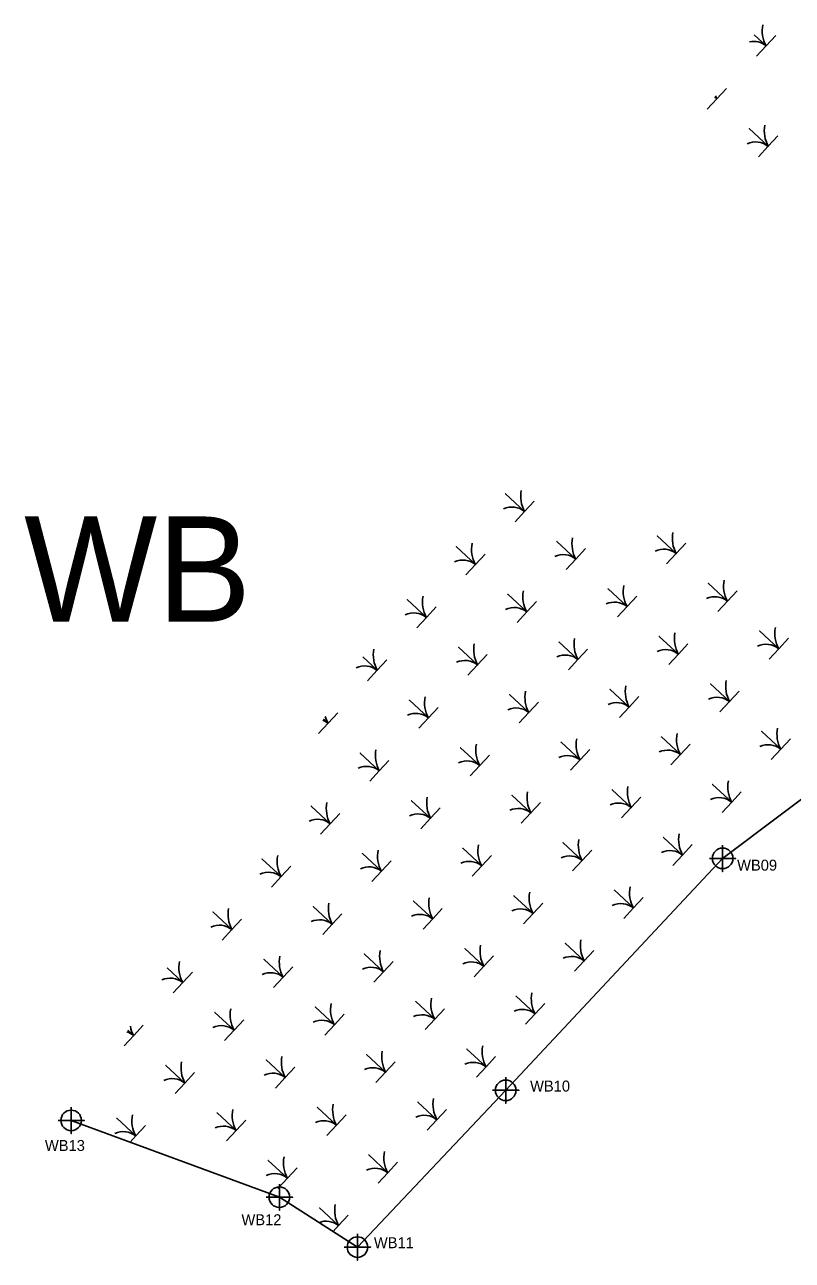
# Model space of a CAD drawing. Extents: x 2130226 to 2130625, y 149525 to 150037.
# Drawn here: x 2130226.4 to 2130401.2, y 149726.8 to 150008.2 of the extents above; entities that cross this region are included whole.
import ezdxf

# ---------------------------------------------------------------- set-up
doc = ezdxf.new("R2010")
doc.units = 0
for name, color, linetype in [('Default', 7, 'Continuous'), ('Exist Environmental Wetland Boundary', 7, 'Continuous'), ('Exist Environmental Wetland Boundary Cogo Number', 7, 'Continuous'), ('Exist Environmental Wetland Boundary Cogo Point CELL', 7, 'Continuous')]:
    doc.layers.add(name, color=color, linetype=linetype)

msp = doc.modelspace()

# ---------------------------------------------------------------- linework, layer by layer
at = {"layer": 'Exist Environmental Wetland Boundary'}
msp.add_lwpolyline([(2130236.94, 149758.63), (2130284.36, 149741.14), (2130302.13, 149729.77), (2130335.9, 149765.49), (2130385.31, 149818.32), (2130425.92, 149848.84), (2130446.29, 149863.99), (2130449.73, 149867.45)], dxfattribs=at)
at = {"layer": 'Exist Environmental Wetland Boundary Cogo Point CELL'}
for points in [[(2130393.01, 150001.04), (2130395.21, 150003.4), (2130392.47, 150005.94)], [(2130392.47, 150005.94), (2130395.21, 150003.4), (2130397.4, 150005.76)], [(2130383.56, 149991.77), (2130384.02, 149991.34), (2130386.21, 149993.7)], [(2130381.82, 149988.98), (2130384.02, 149991.34), (2130383.56, 149991.77)], [(2130393.49, 149978.15), (2130395.69, 149980.51), (2130391.35, 149984.54), (2130395.69, 149980.51), (2130397.88, 149982.88)], [(2130338.02, 149894.97), (2130340.21, 149897.33), (2130335.88, 149901.36), (2130340.21, 149897.33), (2130342.41, 149899.69)], [(2130326.83, 149882.91), (2130329.02, 149885.27), (2130324.69, 149889.3), (2130329.02, 149885.27), (2130331.22, 149887.64)], [(2130349.69, 149884.14), (2130351.88, 149886.5), (2130347.55, 149890.53), (2130351.88, 149886.5), (2130354.08, 149888.87)], [(2130372.55, 149885.37), (2130374.74, 149887.74), (2130370.4, 149891.76), (2130374.74, 149887.74), (2130376.94, 149890.1)], [(2130384.22, 149874.54), (2130386.41, 149876.91), (2130382.07, 149880.93), (2130386.41, 149876.91), (2130388.6, 149879.27)], [(2130338.5, 149872.08), (2130340.69, 149874.44), (2130336.36, 149878.47), (2130340.69, 149874.44), (2130342.89, 149876.81)], [(2130361.36, 149873.31), (2130363.55, 149875.68), (2130359.21, 149879.7), (2130363.55, 149875.68), (2130365.75, 149878.04)], [(2130315.64, 149870.85), (2130317.83, 149873.21), (2130313.5, 149877.24), (2130317.83, 149873.21), (2130320.03, 149875.58)], [(2130395.88, 149863.72), (2130398.08, 149866.08), (2130393.74, 149870.11), (2130398.08, 149866.08), (2130400.27, 149868.45)], [(2130350.17, 149861.25), (2130352.36, 149863.62), (2130348.02, 149867.64), (2130352.36, 149863.62), (2130354.56, 149865.98)], [(2130373.03, 149862.48), (2130375.22, 149864.85), (2130370.88, 149868.87), (2130375.22, 149864.85), (2130377.41, 149867.21)], [(2130304.45, 149858.79), (2130306.64, 149861.15), (2130303.34, 149864.22)], [(2130303.34, 149864.22), (2130306.64, 149861.15), (2130308.84, 149863.52)], [(2130327.31, 149860.02), (2130329.5, 149862.38), (2130325.17, 149866.41), (2130329.5, 149862.38), (2130331.7, 149864.75)], [(2130384.69, 149851.66), (2130386.89, 149854.02), (2130382.55, 149858.05), (2130386.89, 149854.02), (2130389.08, 149856.39)], [(2130338.98, 149849.19), (2130341.17, 149851.56), (2130336.83, 149855.58), (2130341.17, 149851.56), (2130343.37, 149853.92)], [(2130361.84, 149850.43), (2130364.03, 149852.79), (2130359.69, 149856.81), (2130364.03, 149852.79), (2130366.22, 149855.15)], [(2130316.12, 149847.96), (2130318.31, 149850.33), (2130313.98, 149854.35), (2130318.31, 149850.33), (2130320.51, 149852.69)], [(2130293.26, 149846.73), (2130295.45, 149849.09), (2130294.43, 149850.05)], [(2130294.43, 149850.05), (2130295.45, 149849.09), (2130297.65, 149851.46)], [(2130396.36, 149840.83), (2130398.56, 149843.19), (2130394.22, 149847.22), (2130398.56, 149843.19), (2130400.75, 149845.56)], [(2130350.65, 149838.37), (2130352.84, 149840.73), (2130348.5, 149844.76), (2130352.84, 149840.73), (2130355.03, 149843.09)], [(2130373.5, 149839.6), (2130375.7, 149841.96), (2130371.36, 149845.99), (2130375.7, 149841.96), (2130377.89, 149844.33)], [(2130304.93, 149835.9), (2130307.12, 149838.27), (2130302.79, 149842.29), (2130307.12, 149838.27), (2130309.32, 149840.63)], [(2130327.79, 149837.13), (2130329.98, 149839.5), (2130325.64, 149843.52), (2130329.98, 149839.5), (2130332.18, 149841.86)], [(2130362.31, 149827.54), (2130364.51, 149829.9), (2130360.17, 149833.93), (2130364.51, 149829.9), (2130366.7, 149832.27)], [(2130385.17, 149828.77), (2130387.37, 149831.14), (2130383.03, 149835.16), (2130387.37, 149831.14), (2130389.56, 149833.5)], [(2130293.74, 149823.84), (2130295.93, 149826.21), (2130291.6, 149830.23), (2130295.93, 149826.21), (2130298.13, 149828.57)], [(2130316.6, 149825.07), (2130318.79, 149827.44), (2130314.45, 149831.46), (2130318.79, 149827.44), (2130320.99, 149829.8)], [(2130339.46, 149826.31), (2130341.65, 149828.67), (2130337.31, 149832.7), (2130341.65, 149828.67), (2130343.84, 149831.04)], [(2130351.12, 149815.48), (2130353.32, 149817.84), (2130348.98, 149821.87), (2130353.32, 149817.84), (2130355.51, 149820.21)], [(2130373.98, 149816.71), (2130376.18, 149819.08), (2130371.84, 149823.1), (2130376.18, 149819.08), (2130378.37, 149821.44)], [(2130305.41, 149813.02), (2130307.6, 149815.38), (2130303.26, 149819.4), (2130307.6, 149815.38), (2130309.8, 149817.74)], [(2130328.27, 149814.25), (2130330.46, 149816.61), (2130326.12, 149820.64), (2130330.46, 149816.61), (2130332.65, 149818.98)], [(2130385.31, 149821.32), (2130385.31, 149815.32), (2130385.31, 149818.32), (2130388.31, 149818.32), (2130382.31, 149818.32)], [(2130282.55, 149811.78), (2130284.74, 149814.15), (2130280.41, 149818.17), (2130284.74, 149814.15), (2130286.94, 149816.51)], [(2130362.79, 149804.65), (2130364.99, 149807.02), (2130360.65, 149811.04), (2130364.99, 149807.02), (2130367.18, 149809.38)], [(2130317.08, 149802.19), (2130319.27, 149804.55), (2130314.93, 149808.58), (2130319.27, 149804.55), (2130321.46, 149806.92)], [(2130339.93, 149803.42), (2130342.13, 149805.78), (2130337.79, 149809.81), (2130342.13, 149805.78), (2130344.32, 149808.15)], [(2130271.36, 149799.72), (2130273.55, 149802.09), (2130269.22, 149806.11), (2130273.55, 149802.09), (2130275.75, 149804.45)], [(2130294.22, 149800.96), (2130296.41, 149803.32), (2130292.07, 149807.35), (2130296.41, 149803.32), (2130298.61, 149805.68)], [(2130351.6, 149792.59), (2130353.8, 149794.96), (2130349.46, 149798.98), (2130353.8, 149794.96), (2130355.99, 149797.32)], [(2130305.89, 149790.13), (2130308.08, 149792.49), (2130303.74, 149796.52), (2130308.08, 149792.49), (2130310.27, 149794.86)], [(2130328.74, 149791.36), (2130330.94, 149793.73), (2130326.6, 149797.75), (2130330.94, 149793.73), (2130333.13, 149796.09)], [(2130260.17, 149787.66), (2130262.36, 149790.03), (2130258.78, 149793.36)], [(2130258.78, 149793.36), (2130262.36, 149790.03), (2130264.56, 149792.39)], [(2130283.03, 149788.9), (2130285.22, 149791.26), (2130280.88, 149795.29), (2130285.22, 149791.26), (2130287.42, 149793.63)], [(2130317.55, 149779.3), (2130319.75, 149781.67), (2130315.41, 149785.69), (2130319.75, 149781.67), (2130321.94, 149784.03)], [(2130340.41, 149780.53), (2130342.61, 149782.9), (2130338.27, 149786.92), (2130342.61, 149782.9), (2130344.8, 149785.26)], [(2130271.84, 149776.84), (2130274.03, 149779.2), (2130269.69, 149783.23), (2130274.03, 149779.2), (2130276.23, 149781.57)], [(2130294.7, 149778.07), (2130296.89, 149780.43), (2130292.55, 149784.46), (2130296.89, 149780.43), (2130299.08, 149782.8)], [(2130249.86, 149779.18), (2130251.17, 149777.97), (2130253.37, 149780.33)], [(2130248.98, 149775.61), (2130251.17, 149777.97), (2130249.86, 149779.18)], [(2130306.36, 149767.24), (2130308.56, 149769.61), (2130304.22, 149773.63), (2130308.56, 149769.61), (2130310.75, 149771.97)], [(2130329.22, 149768.47), (2130331.42, 149770.84), (2130327.08, 149774.86), (2130331.42, 149770.84), (2130333.61, 149773.2)], [(2130260.65, 149764.78), (2130262.84, 149767.14), (2130258.5, 149771.17), (2130262.84, 149767.14), (2130265.04, 149769.51)], [(2130283.51, 149766.01), (2130285.7, 149768.37), (2130281.36, 149772.4), (2130285.7, 149768.37), (2130287.89, 149770.74)], [(2130335.9, 149768.49), (2130335.9, 149762.49), (2130335.9, 149765.49), (2130338.9, 149765.49), (2130332.9, 149765.49)], [(2130318.03, 149756.42), (2130320.23, 149758.78), (2130315.89, 149762.8), (2130320.23, 149758.78), (2130322.42, 149761.14)], [(2130236.94, 149761.63), (2130236.94, 149755.63), (2130236.94, 149758.63), (2130239.94, 149758.63), (2130233.94, 149758.63)], [(2130272.32, 149753.95), (2130274.51, 149756.32), (2130270.17, 149760.34), (2130274.51, 149756.32), (2130276.7, 149758.68)], [(2130295.17, 149755.18), (2130297.37, 149757.55), (2130293.03, 149761.57), (2130297.37, 149757.55), (2130299.56, 149759.91)], [(2130250.35, 149753.68), (2130251.65, 149755.08), (2130247.31, 149759.11), (2130251.65, 149755.08), (2130253.85, 149757.45)], [(2130283.98, 149743.12), (2130286.18, 149745.49), (2130281.84, 149749.51), (2130286.18, 149745.49), (2130288.37, 149747.85)], [(2130306.84, 149744.36), (2130309.04, 149746.72), (2130304.7, 149750.75), (2130309.04, 149746.72), (2130311.23, 149749.08)], [(2130284.36, 149744.14), (2130284.36, 149738.14), (2130284.36, 149741.14), (2130287.36, 149741.14), (2130281.36, 149741.14)], [(2130296.59, 149733.31), (2130297.85, 149734.66), (2130293.51, 149738.69), (2130297.85, 149734.66), (2130300.04, 149737.03)], [(2130302.13, 149732.77), (2130302.13, 149726.77), (2130302.13, 149729.77), (2130305.13, 149729.77), (2130299.13, 149729.77)]]:
    msp.add_lwpolyline(points, dxfattribs=at)
for centre in [(2130385.31, 149818.32), (2130335.9, 149765.49), (2130236.94, 149758.63), (2130284.36, 149741.14), (2130302.13, 149729.77)]:
    msp.add_circle(centre, 2.34, dxfattribs=at)
for centre, radius, start, end in [((2130401.53, 150006.87), 7.21, 169.2688, 208.7635), ((2130392.32, 149999.8), 4.61, 51.2816, 100.8527), ((2130381.13, 149987.74), 4.61, 51.2816, 58.9988), ((2130390.34, 149994.81), 7.21, 202.9513, 208.7635), ((2130402.01, 149983.98), 7.21, 169.2688, 208.7635), ((2130392.8, 149976.91), 4.61, 51.2816, 114.6763), ((2130346.53, 149900.8), 7.21, 169.2688, 208.7635), ((2130337.33, 149893.73), 4.61, 51.2816, 114.6763), ((2130381.06, 149891.2), 7.21, 169.2688, 208.7635), ((2130335.34, 149888.74), 7.21, 169.2688, 208.7635), ((2130358.2, 149889.97), 7.21, 169.2688, 208.7635), ((2130326.14, 149881.67), 4.61, 51.2816, 114.6763), ((2130349, 149882.9), 4.61, 51.2816, 114.6763), ((2130371.86, 149884.14), 4.61, 51.2816, 114.6763), ((2130392.73, 149880.38), 7.21, 169.2688, 208.7635), ((2130324.15, 149876.68), 7.21, 169.2688, 208.7635), ((2130347.01, 149877.91), 7.21, 169.2688, 208.7635), ((2130369.87, 149879.14), 7.21, 169.2688, 208.7635), ((2130383.52, 149873.31), 4.61, 51.2816, 114.6763), ((2130337.81, 149870.85), 4.61, 51.2816, 114.6763), ((2130360.67, 149872.08), 4.61, 51.2816, 114.6763), ((2130314.95, 149869.61), 4.61, 51.2816, 114.6763), ((2130381.54, 149868.32), 7.21, 169.2688, 208.7635), ((2130404.4, 149869.55), 7.21, 169.2688, 208.7635), ((2130335.82, 149865.85), 7.21, 169.2688, 208.7635), ((2130358.68, 149867.09), 7.21, 169.2688, 208.7635), ((2130395.19, 149862.48), 4.61, 51.2816, 114.6763), ((2130312.96, 149864.62), 7.21, 169.2688, 208.7635), ((2130349.48, 149860.02), 4.61, 51.2816, 114.6763), ((2130372.33, 149861.25), 4.61, 51.2816, 114.6763), ((2130303.76, 149857.55), 4.61, 51.2816, 114.6763), ((2130326.62, 149858.79), 4.61, 51.2816, 114.6763), ((2130393.21, 149857.49), 7.21, 169.2688, 208.7635), ((2130347.49, 149855.03), 7.21, 169.2688, 208.7635), ((2130370.35, 149856.26), 7.21, 169.2688, 208.7635), ((2130324.63, 149853.79), 7.21, 169.2688, 208.7635), ((2130338.29, 149847.96), 4.61, 51.2816, 114.6763), ((2130361.14, 149849.19), 4.61, 51.2816, 114.6763), ((2130384, 149850.42), 4.61, 51.2816, 114.6763), ((2130292.57, 149845.49), 4.61, 51.2816, 68.4476), ((2130301.77, 149852.56), 7.21, 195.245, 208.7635), ((2130315.43, 149846.73), 4.61, 51.2816, 114.6763), ((2130404.88, 149846.66), 7.21, 169.2688, 208.7635), ((2130336.3, 149842.97), 7.21, 169.2688, 208.7635), ((2130359.16, 149844.2), 7.21, 169.2688, 208.7635), ((2130382.02, 149845.43), 7.21, 169.2688, 208.7635), ((2130395.67, 149839.6), 4.61, 51.2816, 114.6763), ((2130313.44, 149841.73), 7.21, 169.2688, 208.7635), ((2130349.95, 149837.13), 4.61, 51.2816, 114.6763), ((2130372.81, 149838.36), 4.61, 51.2816, 114.6763), ((2130304.24, 149834.67), 4.61, 51.2816, 114.6763), ((2130327.1, 149835.9), 4.61, 51.2816, 114.6763), ((2130393.69, 149834.6), 7.21, 169.2688, 208.7635), ((2130347.97, 149832.14), 7.21, 169.2688, 208.7635), ((2130370.83, 149833.37), 7.21, 169.2688, 208.7635), ((2130302.25, 149829.68), 7.21, 169.2688, 208.7635), ((2130325.11, 149830.91), 7.21, 169.2688, 208.7635), ((2130361.62, 149826.3), 4.61, 51.2816, 114.6763), ((2130384.48, 149827.54), 4.61, 51.2816, 114.6763), ((2130293.05, 149822.61), 4.61, 51.2816, 114.6763), ((2130315.91, 149823.84), 4.61, 51.2816, 114.6763), ((2130338.76, 149825.07), 4.61, 51.2816, 114.6763), ((2130359.64, 149821.31), 7.21, 169.2688, 208.7635), ((2130382.5, 149822.54), 7.21, 169.2688, 208.7635), ((2130291.06, 149817.62), 7.21, 169.2688, 208.7635), ((2130313.92, 149818.85), 7.21, 169.2688, 208.7635), ((2130336.78, 149820.08), 7.21, 169.2688, 208.7635), ((2130350.43, 149814.25), 4.61, 51.2816, 114.6763), ((2130373.29, 149815.48), 4.61, 51.2816, 114.6763), ((2130304.72, 149811.78), 4.61, 51.2816, 114.6763), ((2130327.57, 149813.01), 4.61, 51.2816, 114.6763), ((2130281.86, 149810.55), 4.61, 51.2816, 114.6763), ((2130348.45, 149809.25), 7.21, 169.2688, 208.7635), ((2130371.31, 149810.49), 7.21, 169.2688, 208.7635), ((2130302.73, 149806.79), 7.21, 169.2688, 208.7635), ((2130325.59, 149808.02), 7.21, 169.2688, 208.7635), ((2130362.1, 149803.42), 4.61, 51.2816, 114.6763), ((2130279.87, 149805.56), 7.21, 169.2688, 208.7635), ((2130316.38, 149800.95), 4.61, 51.2816, 114.6763), ((2130339.24, 149802.19), 4.61, 51.2816, 114.6763), ((2130270.67, 149798.49), 4.61, 51.2816, 114.6763), ((2130293.53, 149799.72), 4.61, 51.2816, 114.6763), ((2130360.12, 149798.43), 7.21, 169.2688, 208.7635), ((2130314.4, 149795.96), 7.21, 169.2688, 208.7635), ((2130337.26, 149797.19), 7.21, 169.2688, 208.7635), ((2130268.68, 149793.5), 7.21, 169.2688, 208.7635), ((2130291.54, 149794.73), 7.21, 169.2688, 208.7635), ((2130305.19, 149788.89), 4.61, 51.2816, 114.6763), ((2130328.05, 149790.13), 4.61, 51.2816, 114.6763), ((2130350.91, 149791.36), 4.61, 51.2816, 114.6763), ((2130259.48, 149786.43), 4.61, 51.2816, 114.6763), ((2130282.34, 149787.66), 4.61, 51.2816, 114.6763), ((2130348.93, 149786.37), 7.21, 169.2688, 208.7635), ((2130303.21, 149783.9), 7.21, 169.2688, 208.7635), ((2130326.07, 149785.13), 7.21, 169.2688, 208.7635), ((2130280.35, 149782.67), 7.21, 169.2688, 208.7635), ((2130316.86, 149778.07), 4.61, 51.2816, 114.6763), ((2130339.72, 149779.3), 4.61, 51.2816, 114.6763), ((2130257.49, 149781.44), 7.21, 191.0187, 208.7635), ((2130271.15, 149775.6), 4.61, 51.2816, 114.6763), ((2130294, 149776.84), 4.61, 51.2816, 114.6763), ((2130248.29, 149774.37), 4.61, 51.2816, 73.2671), ((2130314.88, 149773.08), 7.21, 169.2688, 208.7635), ((2130337.74, 149774.31), 7.21, 169.2688, 208.7635), ((2130269.16, 149770.61), 7.21, 169.2688, 208.7635), ((2130292.02, 149771.84), 7.21, 169.2688, 208.7635), ((2130328.53, 149767.24), 4.61, 51.2816, 114.6763), ((2130259.96, 149763.54), 4.61, 51.2816, 114.6763), ((2130282.81, 149764.78), 4.61, 51.2816, 114.6763), ((2130305.67, 149766.01), 4.61, 51.2816, 114.6763), ((2130303.69, 149761.02), 7.21, 169.2688, 208.7635), ((2130326.55, 149762.25), 7.21, 169.2688, 208.7635), ((2130257.97, 149758.55), 7.21, 169.2688, 208.7635), ((2130280.83, 149759.78), 7.21, 169.2688, 208.7635), ((2130317.34, 149755.18), 4.61, 51.2816, 114.6763), ((2130271.62, 149752.72), 4.61, 51.2816, 114.6763), ((2130294.48, 149753.95), 4.61, 51.2816, 114.6763), ((2130248.77, 149751.48), 4.61, 51.2816, 114.6763), ((2130315.36, 149750.19), 7.21, 169.2688, 208.7635), ((2130292.5, 149748.96), 7.21, 169.2688, 208.7635), ((2130283.29, 149741.89), 4.61, 51.2816, 114.6763), ((2130306.15, 149743.12), 4.61, 51.2816, 114.6763), ((2130304.17, 149738.13), 7.21, 169.2688, 208.7635), ((2130294.96, 149731.06), 4.61, 51.2816, 110.4764)]:
    msp.add_arc(centre, radius, start, end, dxfattribs=at)

# ---------------------------------------------------------------- texts
at = {"layer": 'Default'}
msp.add_text('WB', height=24, dxfattribs=at).set_placement((2130226.22, 149872.2))
at = {"layer": 'Exist Environmental Wetland Boundary Cogo Number'}
for s, p in [('WB09', (2130388.6, 149815.52)), ('WB10', (2130341.45, 149765.2)), ('WB13', (2130230.96, 149751.66)), ('WB12', (2130275.72, 149734.75)), ('WB11', (2130305.88, 149729.52))]:
    msp.add_text(s, height=2.5, dxfattribs=at).set_placement(p)

doc.saveas('drawing.dxf')
